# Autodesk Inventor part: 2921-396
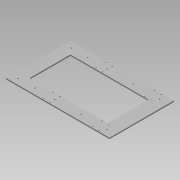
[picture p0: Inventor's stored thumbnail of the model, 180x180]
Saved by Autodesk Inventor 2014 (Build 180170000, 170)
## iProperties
Company: NHTSA/VRTC
Created: 2012-03
Part Number: 2921-396
Material: Steel
Document SubType Name: Modeling
Designer: Mike Vanvoorhis
Density: 7.85 g/cm^3
Project: CHILD SIDE IMPACT SLED
Description: RAIL BEARING MOUNT PLATE
Mass: 14126.7 g
Surface Area: 4391.74 cm^2
Volume: 1799.58 cm^3
Appearance: Steel
Stock Number: PL 9.0 (3/8") x 481.0 (18 15/16") x 787.0 (30 15/16")
DESIGN DATE: 2012-11-05
Author: Dave Walker
Title: Rail Bearing Mount Plate
Subject: Child Side Impact Sled
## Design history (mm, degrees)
sketch "Sketch1"
  geometry: L1 (-303.5, 155)-(291, 155); L2 (291, 155)-(291, -155); L3 (291, -155)-(-303.5, -155); L4 (-303.5, -155)-(-303.5, 155); L5 (-393.5, 245)-(393.5, 245); L6 (393.5, 245)-(393.5, -245); L7 (393.5, -245)-(-393.5, -245); L8 (-393.5, -245)-(-393.5, 245); L9 (0, 343)-(0, -343) reference; L10 (-550.9, 0)-(550.9, 0) reference
  constraints: 16 end point, 4 parallel, 2 horizontal, 2 perpendicular, 2 other
  dimensions: "d0" = 787 distance of L5.start L5.end; "d1" = 490 distance of L7.end L5.start; "d2" = 90 distance between parallel lines of L4 L8; "d3" = 594.5 distance of L1.start L1.end; "d5" = 90 distance between parallel lines of L3 L7; "d6" = 310 distance of L3.end L1.start
extrude "Extrusion1" new body sketch "Sketch1" distance "d7" = 9; taper "d8" = 0 deg
sketch "Sketch2"
  geometry: L1 (-393.5, -245)-(-393.5, 245) reference; L2 (393.5, -245)-(-393.5, -245) reference; L3 (-393.5, 245)-(393.5, 245) reference; C1 r 5.5 at (-216.5, 200) reference; A1 r 5.5 centre (-68.5, 229.45) between (-63, 229.45) and (-74, 229.45) reference; A2 r 5.5 centre (130.5, 229.45) between (136, 229.45) and (125, 229.45) reference; A3 r 5.5 centre (330.5, 229.45) between (336, 229.45) and (325, 229.45) reference; 11 further points
  constraints: 8 horizontal alignment, 8 vertical alignment, 1 coincident
  dimensions: "d9" = 48.9 distance from line of point (-344.6, -200) L1; "d14" = 45 distance from line of point (-344.6, -200) L2; "d15" = 400 distance of point (-344.6, 200) point (-344.6, -200)
hole "Hole1" sketch "Sketch2" at (-344.6, -200), (-216.5, -200), (-68.5, -200), (130.5, -200), (330.5, -200), (-344.6, 200), (-216.5, 200), (-68.5, 200), (130.5, 200), (330.5, 200) diameter "d16" = 7.798; stored, may be unused: countersink angle "d20" = 90 deg, drill point angle "d22" = 118 deg; dims "d17" = 6, "d18" = 4, "d19" = 2, "d21" = 8
sketch "Sketch3"
  geometry: L1 (-393.5, -245)-(-393.5, 245) reference; L2 (393.5, -245)-(-393.5, -245) reference; 17 further points
  constraints: 12 horizontal alignment, 12 vertical alignment
  dimensions: "d23" = 275 distance from line of point (-118.5, -236) L1; "d24" = 327 distance from line of L1 point (-66.5, -236); "d25" = 648 distance from line of point (254.5, -236) L1; "d26" = 700 distance from line of point (306.5, -236) L1; "d27" = 9 distance from line of point (-118.5, -236) L2; "d28" = 81 distance from line of point (-118.5, -164) L2; "d29" = 409 distance from line of point (-118.5, 164) L2; "d30" = 481 distance from line of point (-118.5, 236) L2
hole "Hole2" sketch "Sketch3" at (-118.5, -236), (-66.5, -236), (-118.5, -164), (-66.5, -164), (254.5, -236), (306.5, -236), (254.5, -164), (306.5, -164), (-118.5, 164), (-66.5, 164), (-118.5, 236), (-66.5, 236)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 diameter "d31" = 6.647; stored, may be unused: countersink angle "d35" = 90 deg, drill point angle "d37" = 118 deg; dims "d32" = 6, "d33" = 4, "d34" = 2, "d36" = 8
body "Solid1"
node "Reference1"
node "Reference2"
node "Reference3"
node "Reference4"
